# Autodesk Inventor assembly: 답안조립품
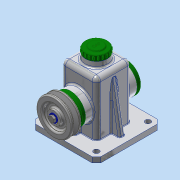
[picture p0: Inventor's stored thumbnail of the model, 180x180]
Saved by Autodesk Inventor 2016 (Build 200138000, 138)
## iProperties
Created: 2018-10
Part Number: 답안조립품
Material: 일반
Document SubType Name: Assembly
Designer: user
Author: user
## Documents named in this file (14)
- C:\Users\user\Desktop\481016V1016\답안조립품.iam
- C:\Users\user\Desktop\481016V1016\본체.ipt
- C:\Users\user\Desktop\481016V1016\베어링 15 x 35 x 11.ipt
- C:\Users\user\Desktop\481016V1016\축.ipt
- C:\Users\user\Desktop\481016V1016\멈춤링 15 x 1.ipt
- C:\Users\user\Desktop\481016V1016\뒤커버.ipt
- C:\Users\user\Desktop\481016V1016\앞커버.ipt
- C:\Users\user\Desktop\481016V1016\볼트 M4 x 10.ipt
- C:\Users\user\Desktop\481016V1016\상부캡.ipt
- C:\Users\user\Desktop\481016V1016\키 5 x 5 x 14.ipt
- C:\Users\user\Desktop\481016V1016\V-벨트풀리.ipt
- C:\Users\user\Desktop\481016V1016\와셔.ipt
- C:\Users\user\Desktop\481016V1016\볼트 M6 x 12.ipt
- C:\Users\user\Desktop\481016V1016\오일실 15 25 7.ipt
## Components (1 placed, 1 different names)
1. V-벨트풀리:1
